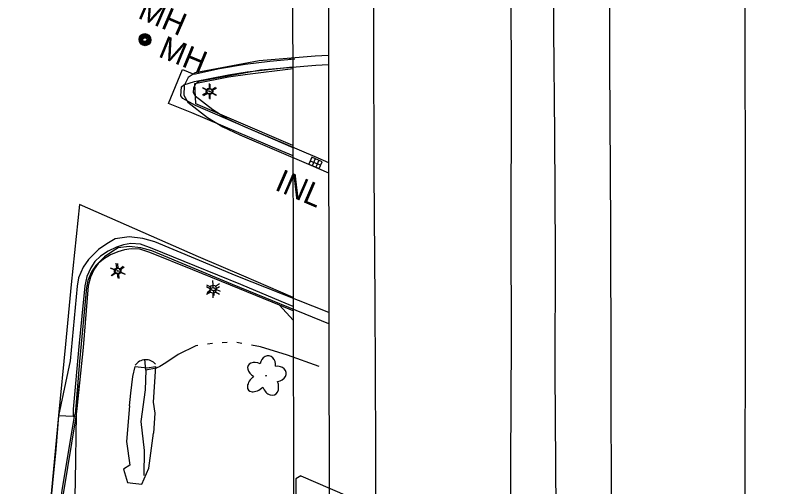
# Model space of a CAD drawing. Extents: x 588843 to 2552415, y 180129 to 269402.
# Drawn here: x 593864.4 to 594066, y 185434.7 to 185559.6 of the extents above; entities that cross this region are included whole.
import ezdxf

# ---------------------------------------------------------------- set-up
doc = ezdxf.new("R2010")
doc.units = 0
for name, color, linetype in [('Default', 7, 'Continuous'), ('E_DRN', 7, 'Continuous'), ('E_DRN_RipRap', 7, 'Continuous'), ('E_DRN_Text', 7, 'Continuous'), ('E_LAND_Vegetation', 7, 'Continuous'), ('E_LTG', 7, 'Continuous'), ('E_RDWY', 7, 'Continuous'), ('E_RDWY_AsphConc', 7, 'Continuous'), ('E_RDWY_C_and_G', 7, 'Continuous'), ('E_RDWY_Gravel', 7, 'Continuous'), ('E_RDWY_PavtEdge', 7, 'Continuous'), ('E_STRUCT', 7, 'Continuous'), ('E_UTL_MH', 7, 'Continuous'), ('E_UTL_MH_Text', 7, 'Continuous'), ('E_WTR_P', 7, 'Continuous'), ('P_RDWY_PavtEdge', 7, 'Continuous')]:
    doc.layers.add(name, color=color, linetype=linetype)

# ---------------------------------------------------------------- blocks, each defined once
blk = doc.blocks.new('LPOL')
at = {"layer": 'Default'}
for p, q in [((-4, 0), (-1.5, 0)), ((-0.75, 1.3), (-2, 3.46)), ((0.75, 1.3), (2, 3.46)), ((1.5, 0), (4, 0)), ((-2, -3.46), (-0.75, -1.3)), ((2, -3.46), (0.75, -1.3))]:
    blk.add_line(p, q, dxfattribs=at)
for radius in [1.5, 1.5, 1.5, 0.125]:
    blk.add_circle((0, 0), radius, dxfattribs=at)
blk = doc.blocks.new('MHT')
at = {"layer": 'E_UTL_MH_Text'}
blk.add_text('MH', height=12, dxfattribs=at).set_placement((-9.81, -6))
blk = doc.blocks.new('MHO')
at = {"layer": 'Default'}
for centre, radius in [((0.08, -0.12), 3), ((0.08, -0.12), 2.43), ((0.07, -0.15), 1.94), ((0.02, -0.16), 1.21)]:
    blk.add_circle(centre, radius, dxfattribs=at)
blk = doc.blocks.new('CULV2_4')
at = {"layer": 'E_DRN'}
blk.add_arc((64.6, 48.4), 80.7, 216.8699, 323.1301, dxfattribs=at)
blk = doc.blocks.new('INLO_3')
at = {"layer": 'E_DRN'}
for p, q in [((6.6, -13.1), (6.6, 0)), ((13.1, -13.1), (13.1, 0)), ((19.7, -6.6), (0, -6.6))]:
    blk.add_line(p, q, dxfattribs=at)
blk.add_lwpolyline([(0, -13.1), (19.7, -13.1), (19.7, 0), (0, 0)], close=True, dxfattribs=at)
blk = doc.blocks.new('INLT_48_2')
at = {"layer": 'E_DRN_Text'}
blk.add_text('INL', height=39.37, dxfattribs=at).set_placement((-36.2, -19.7))
blk = doc.blocks.new('MHO_3')
at = {"layer": 'E_UTL_MH'}
for centre, radius in [((0.3, -0.4), 9.84), ((0.3, -0.4), 7.98), ((0.2, -0.5), 6.35), ((0.1, -0.5), 3.97)]:
    blk.add_circle(centre, radius, dxfattribs=at)
blk = doc.blocks.new('MHT_3')
at = {"layer": 'E_UTL_MH_Text'}
blk.add_text('MH', height=39.37, dxfattribs=at).set_placement((-32.2, -19.7))
blk = doc.blocks.new('LPOL_4')
at = {"layer": 'E_LTG'}
for p, q in [((-13.1, 0), (-4.9, 0)), ((-2.5, 4.3), (-6.6, 11.4)), ((2.5, 4.3), (6.6, 11.4)), ((4.9, 0), (13.1, 0)), ((-6.6, -11.4), (-2.5, -4.3)), ((6.6, -11.4), (2.5, -4.3))]:
    blk.add_line(p, q, dxfattribs=at)
for radius in [4.92, 4.92, 4.92, 0.41]:
    blk.add_circle((0, 0), radius, dxfattribs=at)
blk = doc.blocks.new('DTRE_4')
at = {"layer": 'E_LAND_Vegetation'}
blk.add_circle((-0.6, 0), 0.601, dxfattribs=at)
for centre, major_axis, ratio in [((-6.1, 17.5), (4.5, -16.3), 0.782863), ((-19.3, 0.5), (16.2, -0.4), 0.832022), ((13.3, 9), (-17.3, -9.6), 0.691916), ((-8.2, -17.2), (5.9, 15.9), 0.716896), ((11.6, -12.2), (-16.4, 15), 0.560249)]:
    blk.add_ellipse(centre, major_axis=major_axis, ratio=ratio, start_param=1.570796, end_param=4.712389, dxfattribs=at)

msp = doc.modelspace()

# ---------------------------------------------------------------- linework, layer by layer
at = {"layer": 'E_DRN_RipRap'}
for points in [[(593894.7, 185456.13), (593895.03, 185459.52), (593895.55, 185463.87), (593896.13, 185466.52), (593899.33, 185466.24), (593901.53, 185466.6), (593900.94, 185457.15), (593901.39, 185454.17), (593901.06, 185448.88)], [(593894.7, 185456.13), (593893.91, 185446.69), (593894.76, 185440.42), (593893.12, 185439.38), (593894.1, 185435.81), (593895.53, 185435.64), (593897.93, 185435.43), (593899.79, 185439.62), (593901.06, 185448.88)]]:
    msp.add_lwpolyline(points, dxfattribs=at)
at = {"layer": 'E_RDWY'}
for points in [[(593959.87, 185420.54), (593959.84, 185445.18), (593959.68, 185484.05), (593959.45, 185518.19), (593959.33, 185553.9), (593959.27, 185602.1), (593959.3, 185642.07)], [(593995.63, 185404.88), (593995.6, 185440.77), (593995.74, 185473.91), (593995.68, 185502.41), (593995.72, 185538.18), (593995.67, 185568.02), (593995.66, 185604.47), (593995.5, 185626.87)], [(594022.14, 185393.45), (594022.21, 185425.91), (594022.13, 185466.23), (594022.08, 185503.34), (594021.81, 185547.03), (594021.91, 185590.06), (594021.79, 185615.43)], [(594057.68, 185378.51), (594057.47, 185403.68), (594057.63, 185436.51), (594057.67, 185474.34), (594057.7, 185515.46), (594057.58, 185553.57), (594057.6, 185599.99)], [(593875.84, 185453.5), (593875.18, 185444.55), (593873.42, 185426.77), (593871.63, 185407.61), (593869.74, 185387.1), (593868.31, 185371.28), (593866.46, 185352.19), (593864.94, 185332.65), (593864.52, 185319.97), (593864.65, 185298.49), (593864.53, 185275.87), (593864.59, 185257.56), (593864.77, 185235.68), (593864.91, 185217.64), (593865.21, 185192.03), (593865.51, 185169.15)]]:
    msp.add_lwpolyline(points, dxfattribs=at)
at = {"layer": 'E_RDWY_AsphConc'}
msp.add_lwpolyline([(593880.44, 185453.26), (593877.09, 185432.82), (593874.68, 185401.65), (593869.68, 185351.53), (593868.04, 185328.52), (593868.59, 185305.06), (593869.44, 185252.63), (593869.98, 185207.15), (593870.24, 185177.47), (593870.68, 185147.16), (593871.02, 185130.16)], dxfattribs=at)
at = {"layer": 'E_RDWY_C_and_G'}
for points in [[(593908.71, 185545.25), (593911.68, 185544), (593918.48, 185545.45), (593925.32, 185546.62), (593925.32, 185546.62), (593931.84, 185547.46), (593938.38, 185548.05), (593938.38, 185548.05)], [(593947.32, 185548.95), (593943.77, 185548.78), (593929.01, 185547.53), (593912.07, 185544.37), (593910.16, 185543.07), (593909.12, 185541.01), (593909.03, 185538.45), (593910.14, 185536.55), (593915.3, 185532.53), (593919.37, 185529.99), (593923.83, 185527.93), (593942.69, 185519.89), (593947.37, 185517.87)], [(593947.33, 185546.45), (593943.94, 185546.29), (593929.34, 185545.05), (593913.04, 185542.01), (593912.1, 185541.36), (593911.6, 185540.38), (593911.55, 185539.09), (593912.06, 185538.23), (593916.73, 185534.58), (593920.56, 185532.19), (593924.84, 185530.22), (593943.67, 185522.19), (593947.37, 185520.59)], [(593937.94, 185522.33), (593934.76, 185523.67), (593911.2, 185533.72), (593904.97, 185536.24), (593908.71, 185545.25)], [(593909.05, 185541.12), (593911.91, 185541.99), (593920.89, 185543.82), (593920.89, 185543.82), (593925.82, 185544.56), (593925.82, 185544.56), (593936.97, 185545.81), (593936.97, 185545.81), (593937.89, 185545.9)], [(593911.97, 185541.48), (593920.89, 185543.25), (593920.89, 185543.25), (593925.9, 185544.02), (593925.9, 185544.02), (593937.27, 185545.41), (593937.27, 185545.41), (593937.89, 185545.47)], [(593937.94, 185524.48), (593935.31, 185525.6), (593912.1, 185535.69), (593908.78, 185537.49), (593908.24, 185538.22), (593908.45, 185540.62), (593909.05, 185541.12)], [(593937.93, 185525.08), (593935.45, 185526.12), (593912.2, 185536.12), (593911.97, 185541.48)], [(593912.9, 185495.63), (593881.44, 185509.47), (593879.25, 185488.31), (593877.69, 185472.43), (593875.85, 185453.59), (593879.72, 185453.36), (593880.44, 185453.26)], [(593947.44, 185480.9), (593922.91, 185490.61), (593901.39, 185499.57), (593898.19, 185500.47), (593894.6, 185500.89), (593890.83, 185500.38), (593888.65, 185499.03), (593886.42, 185497.56), (593883.79, 185494.9), (593882.42, 185492.84), (593881.18, 185490.03), (593880.84, 185487.83), (593878.97, 185468.06), (593875.84, 185453.5)], [(593911.95, 185493.24), (593900.64, 185497.85), (593897.57, 185498.95), (593897.57, 185498.95), (593895.05, 185499.11), (593895.05, 185499.11), (593893.09, 185498.78), (593891.21, 185498.16), (593891.21, 185498.16), (593889.03, 185497.09), (593886.99, 185495.75), (593886.99, 185495.75), (593885.53, 185494.39), (593884.4, 185492.73), (593884.4, 185492.73), (593883.41, 185490.4), (593882.84, 185487.93), (593882.84, 185487.93), (593881.26, 185471.87), (593879.79, 185455.22), (593879.72, 185453.36)], [(593947.44, 185477.89), (593921.95, 185488.3), (593900.57, 185497.21), (593897.7, 185498.01), (593894.62, 185498.37), (593891.69, 185497.98), (593890, 185496.92), (593888.02, 185495.62), (593885.74, 185493.31), (593884.62, 185491.63), (593883.6, 185489.32), (593883.32, 185487.52), (593881.46, 185467.84), (593880.32, 185453.86)], [(593911.43, 185492.17), (593900.05, 185496.73), (593897.36, 185497.59), (593897.36, 185497.59), (593895.15, 185497.73), (593895.15, 185497.73), (593893.36, 185497.47), (593891.62, 185496.96), (593891.62, 185496.96), (593889.63, 185496.1), (593887.75, 185495.01), (593887.75, 185495.01), (593886.37, 185493.84), (593885.29, 185492.37), (593885.29, 185492.37), (593884.32, 185490.21), (593883.74, 185487.9), (593883.74, 185487.9), (593882.37, 185471.62), (593880.72, 185455.47), (593880.44, 185453.26)], [(593938.01, 185484.79), (593924.88, 185490.47), (593912.9, 185495.63)], [(593938.01, 185481.31), (593934.38, 185482.78), (593923.76, 185487.14), (593911.43, 185492.17)], [(593938.01, 185482.43), (593934.78, 185483.77), (593924.17, 185488.23), (593911.95, 185493.24)], [(593881.33, 185461.99), (593880.83, 185456.74), (593880.55, 185453.99)]]:
    msp.add_lwpolyline(points, dxfattribs=at)
at = {"layer": 'E_RDWY_Gravel'}
for points in [[(593938.02, 185478.81), (593934.38, 185482.78)], [(593868.28, 185183.24), (593868.29, 185205.46), (593868.14, 185229.51), (593868.36, 185257.81), (593867.92, 185280.99), (593867.98, 185300.88), (593867.76, 185329.05), (593870.2, 185354), (593873.03, 185383.38), (593875.37, 185421.39), (593876.83, 185433.85), (593880.22, 185453.87)], [(593880.55, 185453.99), (593880.27, 185436.18), (593879.73, 185413.27), (593873.51, 185372.17), (593873.98, 185339.4), (593872.71, 185305.48), (593873.23, 185253.41), (593874.93, 185203.22), (593876.95, 185154.58), (593875.43, 185130.24)]]:
    msp.add_lwpolyline(points, dxfattribs=at)
at = {"layer": 'E_RDWY_PavtEdge'}
msp.add_lwpolyline([(593875.85, 185453.59), (593873.92, 185432.86), (593870.99, 185400.68), (593866.59, 185351.79), (593864.42, 185328.6), (593864.71, 185305.3), (593865.19, 185252.78), (593865.69, 185207.57), (593865.81, 185180.99), (593866.2, 185154.42), (593866.2, 185154.42), (593866.82, 185130.11), (593866.82, 185130.11)], dxfattribs=at)
at = {"layer": 'E_STRUCT'}
for points in [[(593947.53, 185425.93), (594007.57, 185399.67), (594069.43, 185373.6), (594069.03, 185595.2), (594007.48, 185621.74), (593947.15, 185647.44), (593947.53, 185425.93)], [(593937.6, 185645.83), (593937.74, 185594.93), (593937.91, 185537.56), (593938.1, 185432.27)], [(594007.57, 185399.67), (594007.57, 185428.21), (594007.32, 185465.26), (594007.38, 185496.34), (594007.27, 185528.01), (594006.95, 185555.68), (594007.15, 185580.26), (594007.06, 185599.87), (594007.48, 185621.74)], [(593940.03, 185437.58), (593938.7, 185436.78), (593938.47, 185381.39)], [(593940.03, 185437.58), (594091.04, 185372.39), (594091.42, 185371.08), (594091.82, 185162.88), (594092.22, 184996.64), (594092.65, 184834.31), (594092.95, 184677.06)]]:
    msp.add_lwpolyline(points, dxfattribs=at)
at = {"layer": 'E_WTR_P'}
for points in [[(593912.73, 185472.14), (593912.21, 185472.07), (593907.57, 185469.7), (593904.32, 185467.54), (593902.66, 185466.6), (593901.76, 185466.15), (593898.98, 185465.58), (593898.72, 185468.52)], [(593916.6, 185472.67), (593915.31, 185472.49)], [(593920.49, 185472.89), (593919.19, 185472.82)], [(593924.37, 185472.69), (593923.09, 185472.94)], [(593944.9, 185466.53), (593936.45, 185469.58), (593929.31, 185471.74), (593926.92, 185472.2)], [(593898.98, 185465.58), (593898.81, 185460.34), (593897.67, 185451.96), (593898.53, 185444.29), (593898.47, 185437.69)]]:
    msp.add_lwpolyline(points, dxfattribs=at)
at = {"layer": 'P_RDWY_PavtEdge'}
msp.add_lwpolyline([(593937.88, 185547.98), (593936.88, 185547.83)], dxfattribs=at)

# ---------------------------------------------------------------- block references
at = {"layer": 'E_DRN'}
for name, p, xscale, yscale, rotation in [('INLO_3', (593944.87, 185518.95), 0.1524003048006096, 0.15240030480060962, 156.65618338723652), ('CULV2_4', (593901.58, 185467.14), 0.041831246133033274, 0.041831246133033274, -177.2133558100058)]:
    msp.add_blockref(name, p, dxfattribs=dict(at, xscale=xscale, yscale=yscale, rotation=rotation))
at = {"layer": 'E_DRN_Text', "xscale": 0.1524003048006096, "yscale": 0.15240030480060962, "rotation": -23.343816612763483}
msp.add_blockref('INLT_48_2', (593939.09, 185514.02), dxfattribs=at)
at = {"layer": 'E_LAND_Vegetation', "xscale": 0.1524003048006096, "yscale": 0.1524003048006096, "rotation": -97.36026881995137}
msp.add_blockref('DTRE_4', (593930.8, 185464.02), dxfattribs=at)
at = {"layer": 'E_LTG'}
for name, p, xscale, yscale, rotation in [('LPOL', (593915.72, 185539.49), 0.5000000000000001, 0.5, -89.67337617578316), ('LPOL_4', (593915.94, 185539.37), 0.1524003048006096, 0.1524003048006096, -89.2544447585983), ('LPOL', (593891.43, 185491.9), 0.49999999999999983, 0.49999999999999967, -22.215816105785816), ('LPOL_4', (593891.65, 185491.81), 0.1524003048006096, 0.15240030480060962, -84.36014555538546), ('LPOL_4', (593916.83, 185487.36), 0.1524003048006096, 0.15240030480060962, -84.36014555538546), ('LPOL', (593916.74, 185486.72), 0.5000000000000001, 0.5, -89.67337617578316)]:
    msp.add_blockref(name, p, dxfattribs=dict(at, xscale=xscale, yscale=yscale, rotation=rotation))
at = {"layer": 'E_UTL_MH'}
for name, p, xscale, yscale, rotation in [('MHO', (593898.7, 185553.29), 0.49999999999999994, 0.5000000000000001, -23.33669759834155), ('MHO_3', (593898.78, 185553.09), 0.15240030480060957, 0.15240030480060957, -22.40034978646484)]:
    msp.add_blockref(name, p, dxfattribs=dict(at, xscale=xscale, yscale=yscale, rotation=rotation))
at = {"layer": 'E_UTL_MH_Text'}
for name, p, xscale, yscale, rotation in [('MHT', (593902.28, 185559.76), 0.49999999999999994, 0.5000000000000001, -23.33669759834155), ('MHT_3', (593907.7, 185549.63), 0.15240030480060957, 0.15240030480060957, -22.40034978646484)]:
    msp.add_blockref(name, p, dxfattribs=dict(at, xscale=xscale, yscale=yscale, rotation=rotation))

doc.saveas('drawing.dxf')
